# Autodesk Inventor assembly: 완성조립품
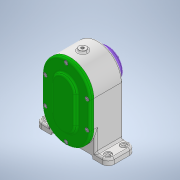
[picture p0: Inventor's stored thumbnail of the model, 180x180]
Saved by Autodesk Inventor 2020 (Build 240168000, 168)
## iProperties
Created: 2021-05
Part Number: 완성조립품
Document SubType Name: Assembly
Designer: Owner
Author: Owner
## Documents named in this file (15)
- C:\Users\Owner\Desktop\710507V1013\완성조립품.iam
- C:\Users\Owner\Desktop\710507V1013\1-본체.ipt
- C:\Users\Owner\Desktop\710507V1013\베어링 6001.ipt
- 베어링 6001.ipt
- C:\Users\Owner\Desktop\710507V1013\축 A.ipt
- C:\Users\Owner\Desktop\710507V1013\축 B.ipt
- C:\Users\Owner\Desktop\710507V1013\키 5 x 5 x 12.ipt
- C:\Users\Owner\Desktop\710507V1013\키 4 x 4 x 12.ipt
- C:\Users\Owner\Desktop\710507V1013\칼라.ipt
- C:\Users\Owner\Desktop\710507V1013\커버 A.ipt
- C:\Users\Owner\Desktop\710507V1013\베어링 6002.ipt
- 베어링 6002.ipt
- C:\Users\Owner\Desktop\710507V1013\커버 B.ipt
- C:\Users\Owner\Desktop\710507V1013\오일 실 12 22 7.ipt
- C:\Users\Owner\Desktop\710507V1013\볼트 M4.ipt
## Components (1 placed, 1 different names)
1. 1-본체:1
